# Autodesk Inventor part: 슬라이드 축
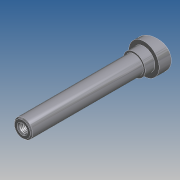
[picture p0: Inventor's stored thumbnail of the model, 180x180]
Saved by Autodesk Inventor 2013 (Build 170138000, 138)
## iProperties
Company: 한국ATC센터
Created: 2012-05
Part Number: 슬라이드 축
Document SubType Name: 모델링
Designer: KYOUNG IL JANG
Mass: 169.556 g
Surface Area: 67.5855 cm^2
Volume: 21.572 cm^3
Density: 7.86 g/cm^3
Material: 강, 연강
변환 표준: STEP AP214IS
파일 이름: C:\Users\SeoGD\Desktop\?쒗뿕\異?stp
전처리기: Build: 253, Release: 2010 SP1 - Date: Wed 07/29/2009
전송 단위: 밀리미터
불확실성: 0.01
Author: KYOUNG IL JANG
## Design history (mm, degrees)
sketch "스케치1"
  geometry: L1 (0, 100)-(7.5, 100); L2 (7.5, 100)-(7.5, 0); L3 (7.5, 0)-(12.5, 0); L4 (12.5, 0)-(12.5, -17); L5 (12.5, -17)-(0, -17); L6 (0, -17)-(0, 100); 1 further point
  constraints: 12 end point, 2 parallel, 2 point on line, 1 perpendicular, 1 vertical
  dimensions: "d0" = 100 distance from line of L1 point (0, 0); "d1" = 15 diameter of L2 L6; "d2" = 25 diameter of L4 L6; "d3" = 17 distance of L3.end L4.end
revolve "회전1" sketch "스케치1" stored, may be unused: angle "d4" = 90 deg
sketch "스케치2"
  geometry: L1 (12.5, 0)-(12.5, -17) reference; L2 (-12.5, -17)-(12.5, -17) reference; L3 (-12.5, 0)-(-12.5, -17) reference; L4 (12.5, -5)-(-12.5, -11.699); L5 (-12.5, 0)-(12.5, 0) reference; 1 further point
  constraints: 2 end point, 2 point on line
  dimensions: "d5" = 75 deg angle of L1 L4; "d6" = 5 distance from line of L4.start L5
extrude "돌출1" cut sketch "스케치2" stored distance "d7" = 10; taper "d8" = 0 deg
chamfer "모따기1" distance "d9" = 1; stored, may be unused: second distance "d10" = 2, angle "d11" = 45 deg
fillet "모깎기1" dims "d12" = 0.5
hole "구멍1" diameter "d15" = 6.647; stored, may be unused: countersink angle "d19" = 90 deg, drill point angle "d21" = 118 deg; dims "d13" = 10, "d14" = 10, "d16" = 17, "d17" = 4, "d18" = 2, "d20" = 20
chamfer "모따기2" distance "d22" = 1; stored, may be unused: second distance "d23" = 2, angle "d24" = 45 deg
sketch "스케치3"
  geometry: C1 r 9 at (0, 0); 1 further point
  constraints: 1 centre point, 1 coincident
  dimensions: "d25" = 18 diameter of C1
extrude "돌출2" join sketch "스케치3" distance "d26" = 8; taper "d27" = 0 deg
node "솔리드1"
node "솔리드 본체"
node "곡면 본체"
node "솔리드2"
